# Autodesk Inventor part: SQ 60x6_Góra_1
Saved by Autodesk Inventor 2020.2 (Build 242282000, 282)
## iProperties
Created: 2006-08
Part Number: SQ 60x6_Góra_1
Material: Ogólny
Document SubType Name: Modeling
Designer: F.Stasiak
Manufacturer: Standard
Standards Organization: Custom
Stock Number: DIN EN 10210-2 SQ 60x6
Density: 1 g/cm^3
Appearance: Domyślna
Manager: www.cadconsulting.pl
Company: Fabian Stasiak CAD Consulting
G_L: 1000,0 mm
G_W: 60,000 mm
G_H: 60,000 mm
AFG_Item: 60 x 60 x 6
Author: F.Stasiak
Subject: Zbiór ćwiczeń. Autodesk Inventor 2020. Kurs podstawowy
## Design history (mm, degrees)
sketch "AFG_Detailed"
  geometry: L1 (48, 54)-(12, 54); L2 (6, 48)-(6, 12); L3 (12, 6)-(48, 6); L4 (54, 12)-(54, 48); L5 (48, 60)-(12, 60); L6 (0, 48)-(0, 12); L7 (12, 0)-(48, 0); L8 (60, 12)-(60, 48); A1 r 6 centre (48, 48) between (54, 48) and (48, 54); A2 r 12 centre (48, 48) between (60, 48) and (48, 60); A3 r 6 centre (48, 12) between (48, 6) and (54, 12); A4 r 12 centre (48, 12) between (48, 0) and (60, 12); A5 r 12 centre (12, 12) between (0, 12) and (12, 0); A6 r 6 centre (12, 12) between (6, 12) and (12, 6); A7 r 6 centre (12, 48) between (12, 54) and (6, 48); A8 r 12 centre (12, 48) between (12, 60) and (0, 48); 4 further points
  constraints: 16 end point, 16 point on circle, 16 tangent, 8 centre point, 6 point on line, 4 parallel, 2 perpendicular, 1 vertical
  dimensions: "d15" = 60 distance of point (0, 0) point (60, 0) (= GEO_B); "d16" = 6 distance between parallel lines of L7 L3 (= GEO_S); "d17" = 6 distance between parallel lines of L8 L4 (= GEO_S); "d18" = 6 distance between parallel lines of L5 L1 (= GEO_S); "d19" = 6 distance between parallel lines of L6 L2 (= GEO_S); "d20" = 30 distance from line of point (30, 30) L7 (= 0.5 x GEO_H); "d30" = 6 radius of A1 (= GEO_R1 - GEO_S); "GEO_R1" = 12 radius of A2; "d32" = 6 radius of A3 (= GEO_R1 - GEO_S); "d33" = 12 radius of A4 (= GEO_R1); "d34" = 12 radius of A5 (= GEO_R1); "d35" = 6 radius of A6 (= GEO_R1 - GEO_S); "d36" = 6 radius of A7 (= GEO_R1 - GEO_S); "d37" = 12 radius of A8 (= GEO_R1); "d38" = 30 distance from line of L6 point (30, 30) (= 0.5 x GEO_B); "d39" = 60 distance between parallel lines of L7 L5 (= GEO_H)
sketch "AFG_Medium"
  geometry: L1 (54, 54)-(6, 54); L2 (6, 54)-(6, 6); L3 (6, 6)-(54, 6); L4 (54, 6)-(54, 54); L5 (60, 60)-(0, 60); L6 (0, 60)-(0, 0); L7 (0, 0)-(60, 0); L8 (60, 0)-(60, 60); 1 further point
  constraints: 16 end point, 4 parallel, 2 perpendicular, 1 vertical
  dimensions: "GEO_B" = 60 distance of L6.end L7.end; "GEO_S" = 6 distance between parallel lines of L7 L3; "d5" = 6 distance between parallel lines of L8 L4 (= GEO_S); "d6" = 6 distance between parallel lines of L5 L1 (= GEO_S); "d7" = 6 distance between parallel lines of L6 L2 (= GEO_S); "d12" = 30 distance from line of point (30, 30) L7 (= 0.5 x GEO_H); "d40" = 60 distance between parallel lines of L7 L5 (= GEO_H); "d41" = 30 distance from line of L6 point (30, 30) (= 0.5 x GEO_B)
sketch "AFG_Simplified"
  geometry: L1 (60, 60)-(0, 60); L2 (0, 60)-(0, 0); L3 (0, 0)-(60, 0); L4 (60, 0)-(60, 60); 1 further point
  constraints: 8 end point, 2 parallel, 1 perpendicular, 1 vertical
  dimensions: "d23" = 60 distance of L2.end L3.end (= GEO_B); "d28" = 30 distance from line of point (30, 30) L3 (= 0.5 x GEO_H); "d42" = 60 distance between parallel lines of L3 L1 (= GEO_H); "d43" = 30 distance from line of point (30, 30) L2 (= 0.5 x GEO_B)
derived "Szkielet podstawy.ipt"
  sketch "Szkic1"
    geometry: L1 (0, 0)-(1500, 0) reference; L2 (1500, 0)-(1500, 1000) reference; L3 (1500, 1000)-(0, 1000) reference; L4 (0, 1000)-(0, 0) reference
  sketch "Szkic2"
    geometry: L1 (0, 1000)-(0, 0) reference; L2 (0, 0)-(1500, 0) reference; L3 (1500, 0)-(1500, 1000) reference; L4 (500, 1000)-(1500, 1000) reference; L5 (1500, 1000)-(1500, 0) reference; L6 (1500, 0)-(500, 0) reference; L7 (500, 0)-(500, 1000) reference; L8 (1500, 1000)-(0, 1000) reference
node "AFG_StartWorkPoint_SQ 60x6_Góra_1"
node "AFG_EndWorkPoint_SQ 60x6_Góra_1"
node "AFG_HelpAxis"
node "AFG_HelpStart"
node "AFG_HelpEnd"
node "AFG_Midplane"
  node "AFG_Startplane"
  node "AFG_EndPlane"
node "AFG_Profile_AxisX_for_External_Matrix"
extrude "AFG_Detailed_SQ 60x6_Góra_1" join sketch "AFG_Detailed" stored distance "d49" = 0.13; taper "d50" = 0 deg
extrude "AFG_Simplified_SQ 60x6_Góra_1" join sketch "AFG_Simplified" stored distance "d51" = 0.13; taper "d52" = 0 deg
node "AFG_StartWorkPoint_SQ 60x6_Góra_2"
node "AFG_EndWorkPoint_SQ 60x6_Góra_2"
node "AFG_ENDCUTPLANE_SQ 60x6_Góra_1"
node "AFG_StartWorkPoint_SQ 60x6_Góra_4"
node "AFG_EndWorkPoint_SQ 60x6_Góra_4"
node "AFG_STARTCUTPLANE_SQ 60x6_Góra_1"
node "Bryła1"
node "Korpusy bryłowe"
node "Korpusy powierzchniowe"
other parameters: "GEO_H" = 60, "AFG_Origin_X" = 0 (= 0 x GEO_B) [user parameter], "AFG_Origin_Y" = 0 (= 0 x GEO_H) [user parameter], "AFG_IP_X2" = 0 (= 0 x GEO_B) [user parameter], "AFG_IP_Y4" = 0 (= 0 x GEO_H) [user parameter], "AFG_IP_X6" = 0 (= 0 x GEO_B) [user parameter], "AFG_IP_Y8" = 0 (= 0 x GEO_H) [user parameter], "d47" = 0, "d48" = 0, "G_L" = 1000 [user parameter], "d55" = 0, "d58" = 0
